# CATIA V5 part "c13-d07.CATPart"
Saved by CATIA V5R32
Part number: Part1
Bounding box of the stored display mesh (mm): x -49.812 to 35, y -44.222 to 44.222, z 0 to 30
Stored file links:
  D:\PROJECTS\Project 2022\CATIA V5 6R 2022\Resources\Part Files\c13_catia_v5_6r2022_prt\c13_catia_v5-6r2022_figr_13-26 & 27\c13-d07.CATPart
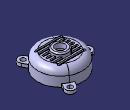
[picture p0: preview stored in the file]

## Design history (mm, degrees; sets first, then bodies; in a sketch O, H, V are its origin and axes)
Body1 (main body)
  Sketch1 on yz-plane, origin (0, 0, 0), H (0, 1, 0), V (0, 0, 1)
    line L1 (0, 0) -> (35, 0)
    line L2 (35, 0) -> (35, 15)
    arc A1 centre (25, 15) radius 10 from (35, 15) to (25, 25) ccw
    line L3 (25, 25) -> (0, 25)
    point P5 (0, 25)
    line L4 (0, 25) -> (0, 0)
    axis line L5 (0, 70.1891) -> (0, -36.6898)
    point P6 (0, 70.1891)
    radius about axis L2 L5 = 35
    distance L1 L3 = 25
    radius A1 = 10
    horizontal: L1 H
    vertical: L2 V, L4 V, L5 V
    tangency: A1 L2, L3 A1
    coincidence: P5 V, P6 V
  Shaft1: profile Sketch1, axis Sketch1.L5, angle 360
  Shell1: ExtOffset 0, Face face of Shaft1, IntOffset 2.5
  Sketch2 on face of Shaft1, origin (0, 0, 0), H (1, 0, 0), V (0, -1, 0)
    projected circle E1 centre (0, 0) radius 35 from edge [face of Shaft1 | face of Shaft1]
    projected arc E2 centre (0, 0) radius 35 from (-34.187, 7.5) to (-34.187, -7.5) ccw from edge [face of Shaft1 | face of Shaft1]
    point P1 (-34.187, 7.5)
    line L1 (-34.187, 7.5) -> (-42.5, 7.5)
    arc A1 centre (-42.5, 0) radius 7.5 from (-42.5, 7.5) to (-42.5, -7.5) ccw
    point P3 (-42.5, 0)
    line L2 (-42.5, -7.5) -> (-34.187, -7.5)
    point P5 (-34.187, -7.5)
    circle A2 centre (-42.5, 0) radius 3.75
    distance P3 V = 42.5
    radius A1 = 7.5
    radius A2 = 3.75
    coincidence: P1 E1, P5 E1, P3 H
    horizontal: L1 H, L2 H
    tangency: A1 L1, L2 A1
  Pad1: profile Sketch2, direction (0, 0, 1), length 5
  CircPattern1: of Pad1, instances 3, angular step 120 {= 360.0*1 deg/CircPattern1.AngularNumber}, axis from face of Shaft1
  Sketch3 on face of Shaft1, origin (0, 0, 25), H (1, 0, 0), V (0, 1, 0)
    construction line L1 (-20, -18) -> (20, -18)
    point P2 (20, -18)
    line L2 (-20, -16.25) -> (20, -16.25)
    line L3 (20, -19.75) -> (-20, -19.75)
    arc A1 centre (20, -18) radius 1.75 from (20, -16.25) to (20, -19.75) cw
    arc A2 centre (-20, -18) radius 1.75 from (-20, -19.75) to (-20, -16.25) cw
    length L1 = 40
    distance H L1 = 18
    distance P2 V = 20
    distance L3 L2 = 3.5
    horizontal: L1 H
    tangency: A1 L2, A2 L2, A1 L3, A2 L3
    parallelism: L1 L2
  Pocket1: profile Sketch3, direction (0, 0, -1), through (limit type 3)
  RectPattern1: of Pocket1, direction 1 instances 7, spacing 6, along yz-plane
  Sketch4 on yz-plane, origin (0, 0, 0), H (0, 1, 0), V (0, 0, 1)
    axis line L1 (0, 0) -> (0, 35.5018)
    point P2 (0, 22.5)
    line L2 (0, 22.5) -> (12.5, 22.5)
    line L3 (12.5, 22.5) -> (12.5, 28)
    arc A1 centre (10.5, 28) radius 2 from (12.5, 28) to (10.5, 30) ccw
    line L4 (10.5, 30) -> (0, 30)
    point P7 (0, 30)
    line L5 (0, 30) -> (0, 22.5)
    reference intersected line E1 (25, 22.5) -> (-25, 22.5) from face of Shell1
    radius about axis L3 L1 = 12.5
    distance L4 L2 = 7.5
    radius A1 = 2
    vertical: L1 V, L3 V, L5 V
    coincidence: P2 L1, P7 L1, L2 E1
    horizontal: L2 H, L4 H
    tangency: A1 L3, L4 A1
  Shaft2: profile Sketch4, axis Sketch4.L1, angle 360
  Sketch5 on face of Shaft2, origin (0, 0, 30), H (1, 0, 0), V (0, 1, 0)
    point P1 (0, 0)
    reference projected circle E1 centre (0, 0) radius 12.5 from edge [face of Shaft2 | face of Shaft2]
    concentricity: P1 E1
  Hole1: placed by Sketch5, at (0, 0, 30) direction (0, 0, -1), diameter 15, through (limit type 3)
